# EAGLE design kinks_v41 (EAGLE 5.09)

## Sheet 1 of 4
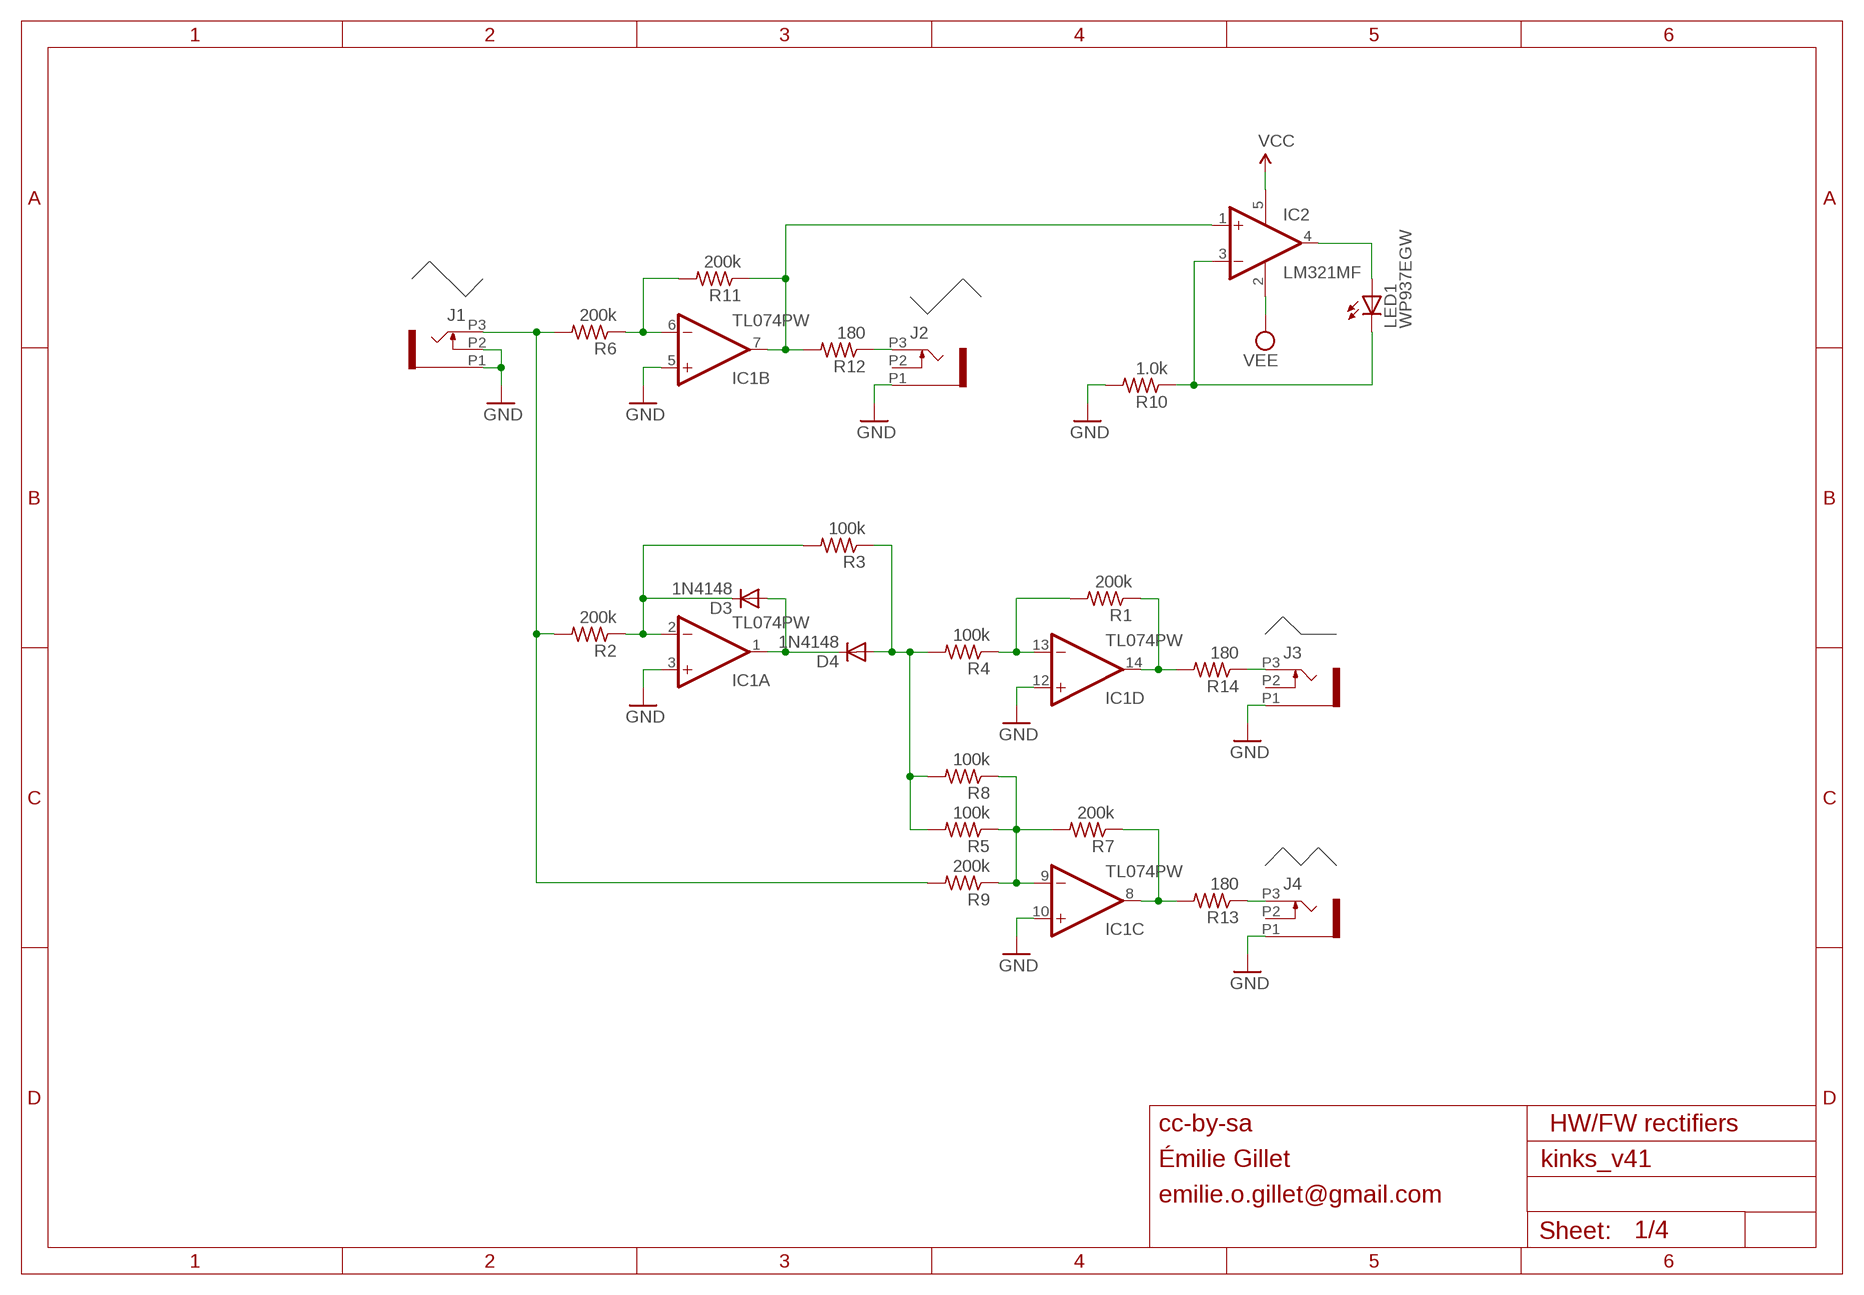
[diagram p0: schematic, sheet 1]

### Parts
D3  1N4148  DIODE-SOD523  [SOD523]
D4  1N4148  DIODE-SOD523  [SOD523]
IC1  TL074PW  [TSSOP14]
IC2  LM321MF  [SOT23-5]
J1  PJ301_THONKICONN6  [WQP_PJ_301M6]
J2  PJ301_THONKICONN6  [WQP_PJ_301M6]
J3  PJ301_THONKICONN6  [WQP_PJ_301M6]
J4  PJ301_THONKICONN6  [WQP_PJ_301M6]
LED1  WP937EGW  LED3MM  [LED3MM]
R1  200k  R-US_R0402  [R0402]
R2  200k  R-US_R0402  [R0402]
R3  100k  R-US_R0402  [R0402]
R4  100k  R-US_R0402  [R0402]
R5  100k  R-US_R0402  [R0402]
R6  200k  R-US_R0402  [R0402]
R7  200k  R-US_R0402  [R0402]
R8  100k  R-US_R0402  [R0402]
R9  200k  R-US_R0402  [R0402]
R10  1.0k  R-US_R0402  [R0402]
R11  200k  R-US_R0402  [R0402]
R12  180  R-US_R0402  [R0402]
R13  180  R-US_R0402  [R0402]
R14  180  R-US_R0402  [R0402]

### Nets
GND: IC1.3(A:+IN) IC1.5(B:+IN) IC1.10(C:+IN) IC1.12(D:+IN) J1.P1 J1.P2 J2.P1 J3.P1 J4.P1 R10.2 ; also sheet 2,3,4
N$9: IC2.3(-IN) LED1.K(C) R10.1
N$11: IC2.4(OUT) LED1.A
N$21: IC1.6(B:-IN) R6.1 R11.2
N$23: IC1.7(B:OUT) IC2.1(+IN) R11.1 R12.2
N$24: J2.P3 R12.1
N$25: D3.C IC1.2(A:-IN) R2.1 R3.2
N$26: D3.A D4.C IC1.1(A:OUT)
N$27: IC1.14(D:OUT) R1.1 R14.2
N$28: IC1.13(D:-IN) R1.2 R4.1
N$32: J3.P3 R14.1
N$33: IC1.9(C:-IN) R5.1 R7.2 R8.1 R9.1
N$34: J4.P3 R13.1
N$35: IC1.8(C:OUT) R7.1 R13.2
N$38: J1.P3 R2.2 R6.2 R9.2
N$39: D4.A R3.1 R4.2 R5.2 R8.2
VCC: IC2.5(V+) ; also sheet 2,3,4
VEE: IC2.2(V-) ; also sheet 2,3,4
Unconnected: J2.P2 J3.P2 J4.P2

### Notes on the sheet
- cc-by-sa | HW/FW rectifiers
- Émilie Gillet
- emilie.o.gillet@gmail.com

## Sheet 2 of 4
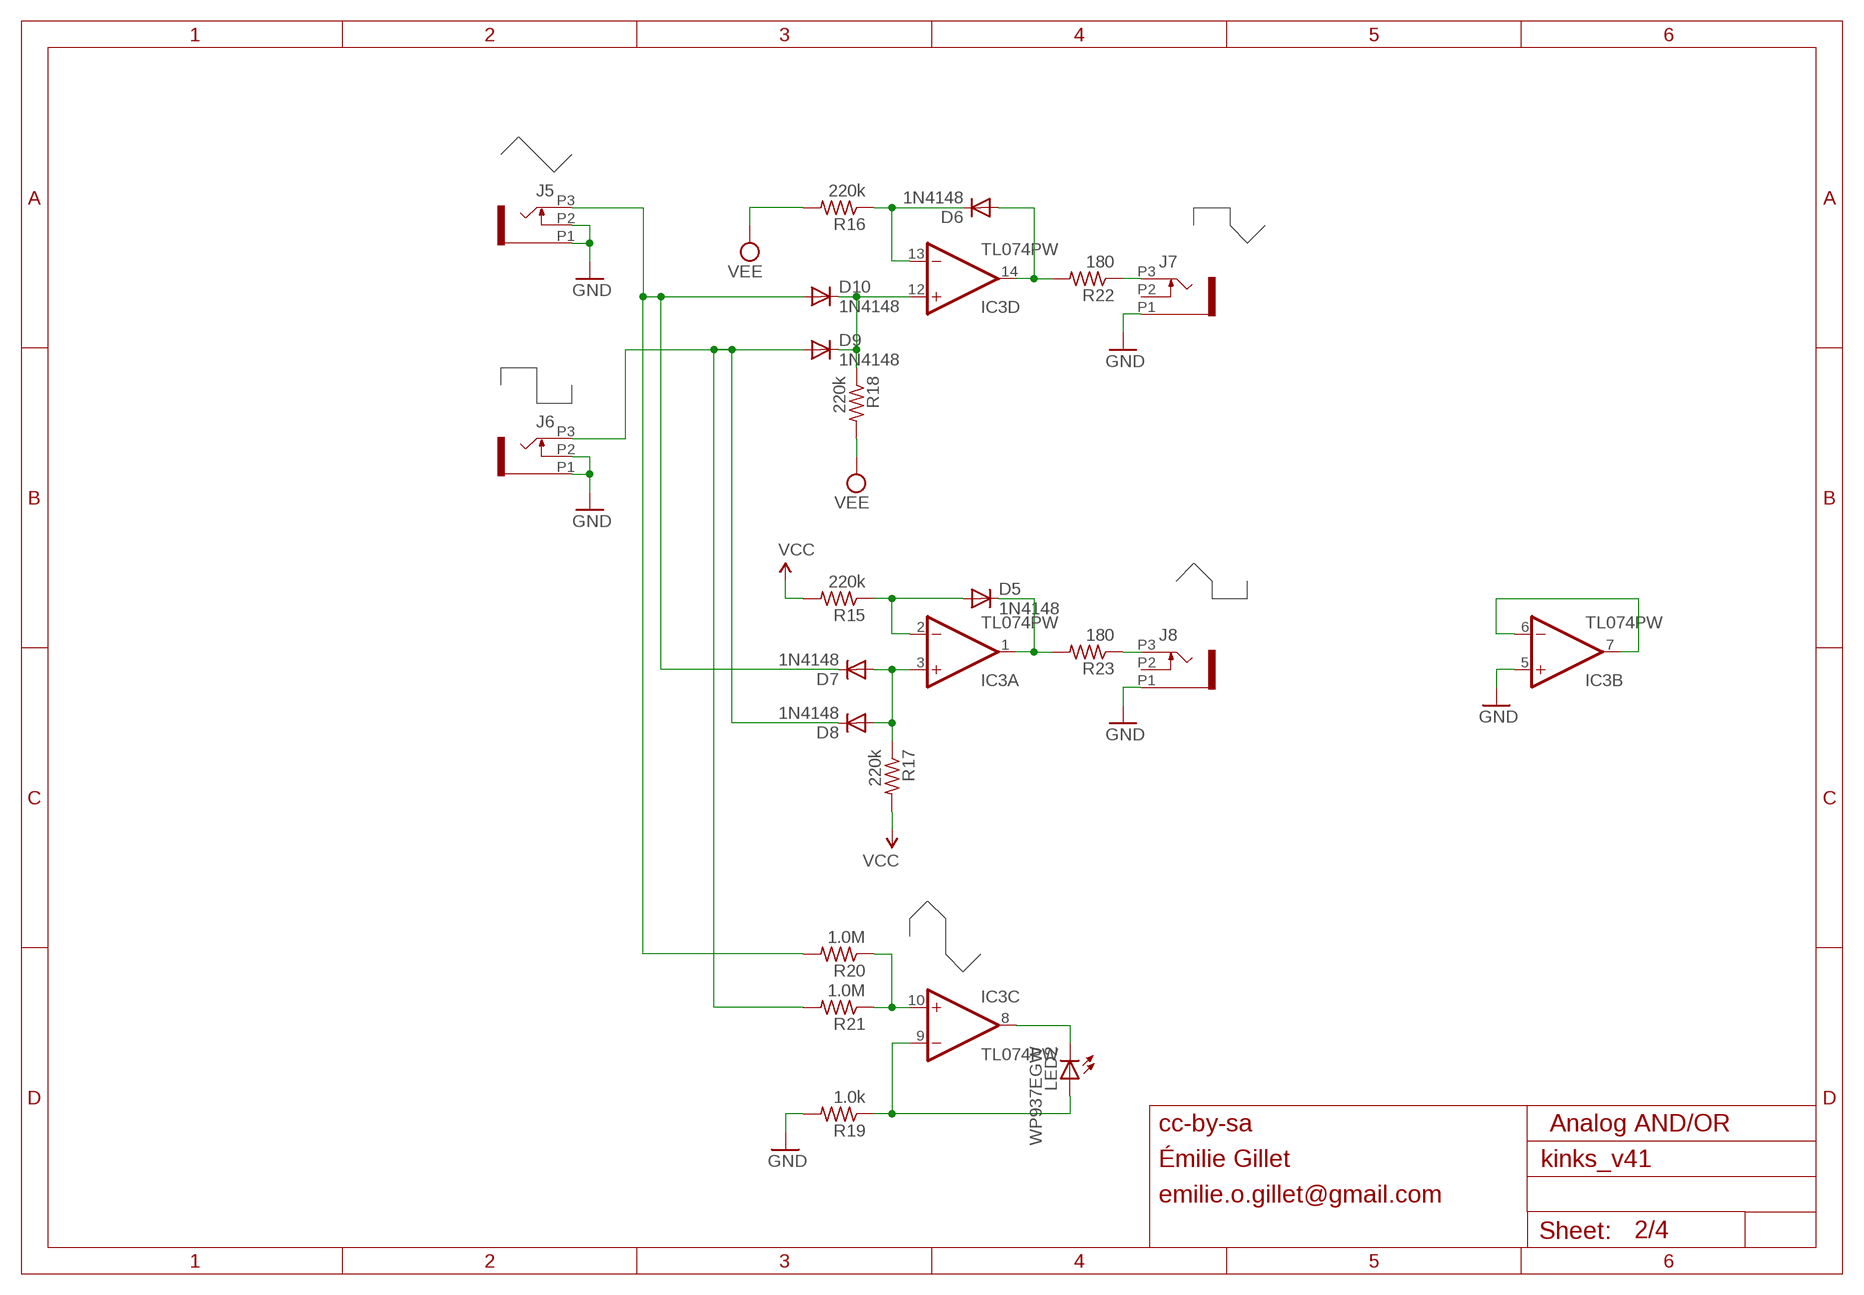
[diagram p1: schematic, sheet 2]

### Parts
D5  1N4148  DIODE-SOD523  [SOD523]
D6  1N4148  DIODE-SOD523  [SOD523]
D7  1N4148  DIODE-SOD523  [SOD523]
D8  1N4148  DIODE-SOD523  [SOD523]
D9  1N4148  DIODE-SOD523  [SOD523]
D10  1N4148  DIODE-SOD523  [SOD523]
IC3  TL074PW  [TSSOP14]
J5  PJ301_THONKICONN6  [WQP_PJ_301M6]
J6  PJ301_THONKICONN6  [WQP_PJ_301M6]
J7  PJ301_THONKICONN6  [WQP_PJ_301M6]
J8  PJ301_THONKICONN6  [WQP_PJ_301M6]
LED2  WP937EGW  LED3MM  [LED3MM]
R15  220k  R-US_R0402  [R0402]
R16  220k  R-US_R0402  [R0402]
R17  220k  R-US_R0402  [R0402]
R18  220k  R-US_R0402  [R0402]
R19  1.0k  R-US_R0402  [R0402]
R20  1.0M  R-US_R0402  [R0402]
R21  1.0M  R-US_R0402  [R0402]
R22  180  R-US_R0402  [R0402]
R23  180  R-US_R0402  [R0402]

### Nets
A: D7.C D10.A J5.P3 R20.2
B: D8.C D9.A J6.P3 R21.2
GND: IC3.5(B:+IN) J5.P1 J5.P2 J6.P1 J6.P2 J7.P1 J8.P1 R19.2 ; also sheet 1,3,4
N$1: D9.C D10.C IC3.12(D:+IN) R18.1
N$2: D6.A IC3.14(D:OUT) R22.2
N$4: D6.C IC3.13(D:-IN) R16.1
N$5: D7.A D8.A IC3.3(A:+IN) R17.1
N$7: IC3.6(B:-IN) IC3.7(B:OUT)
N$10: D5.C IC3.1(A:OUT) R23.2
N$14: IC3.8(C:OUT) LED2.K(C)
N$15: D5.A IC3.2(A:-IN) R15.1
N$17: J8.P3 R23.1
N$18: IC3.10(C:+IN) R20.1 R21.1
N$29: IC3.9(C:-IN) LED2.A R19.1
N$47: J7.P3 R22.1
VCC: R15.2 R17.2 ; also sheet 1,3,4
VEE: R16.2 R18.2 ; also sheet 1,3,4
Unconnected: J7.P2 J8.P2

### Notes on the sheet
- cc-by-sa | Analog AND/OR
- Émilie Gillet
- emilie.o.gillet@gmail.com

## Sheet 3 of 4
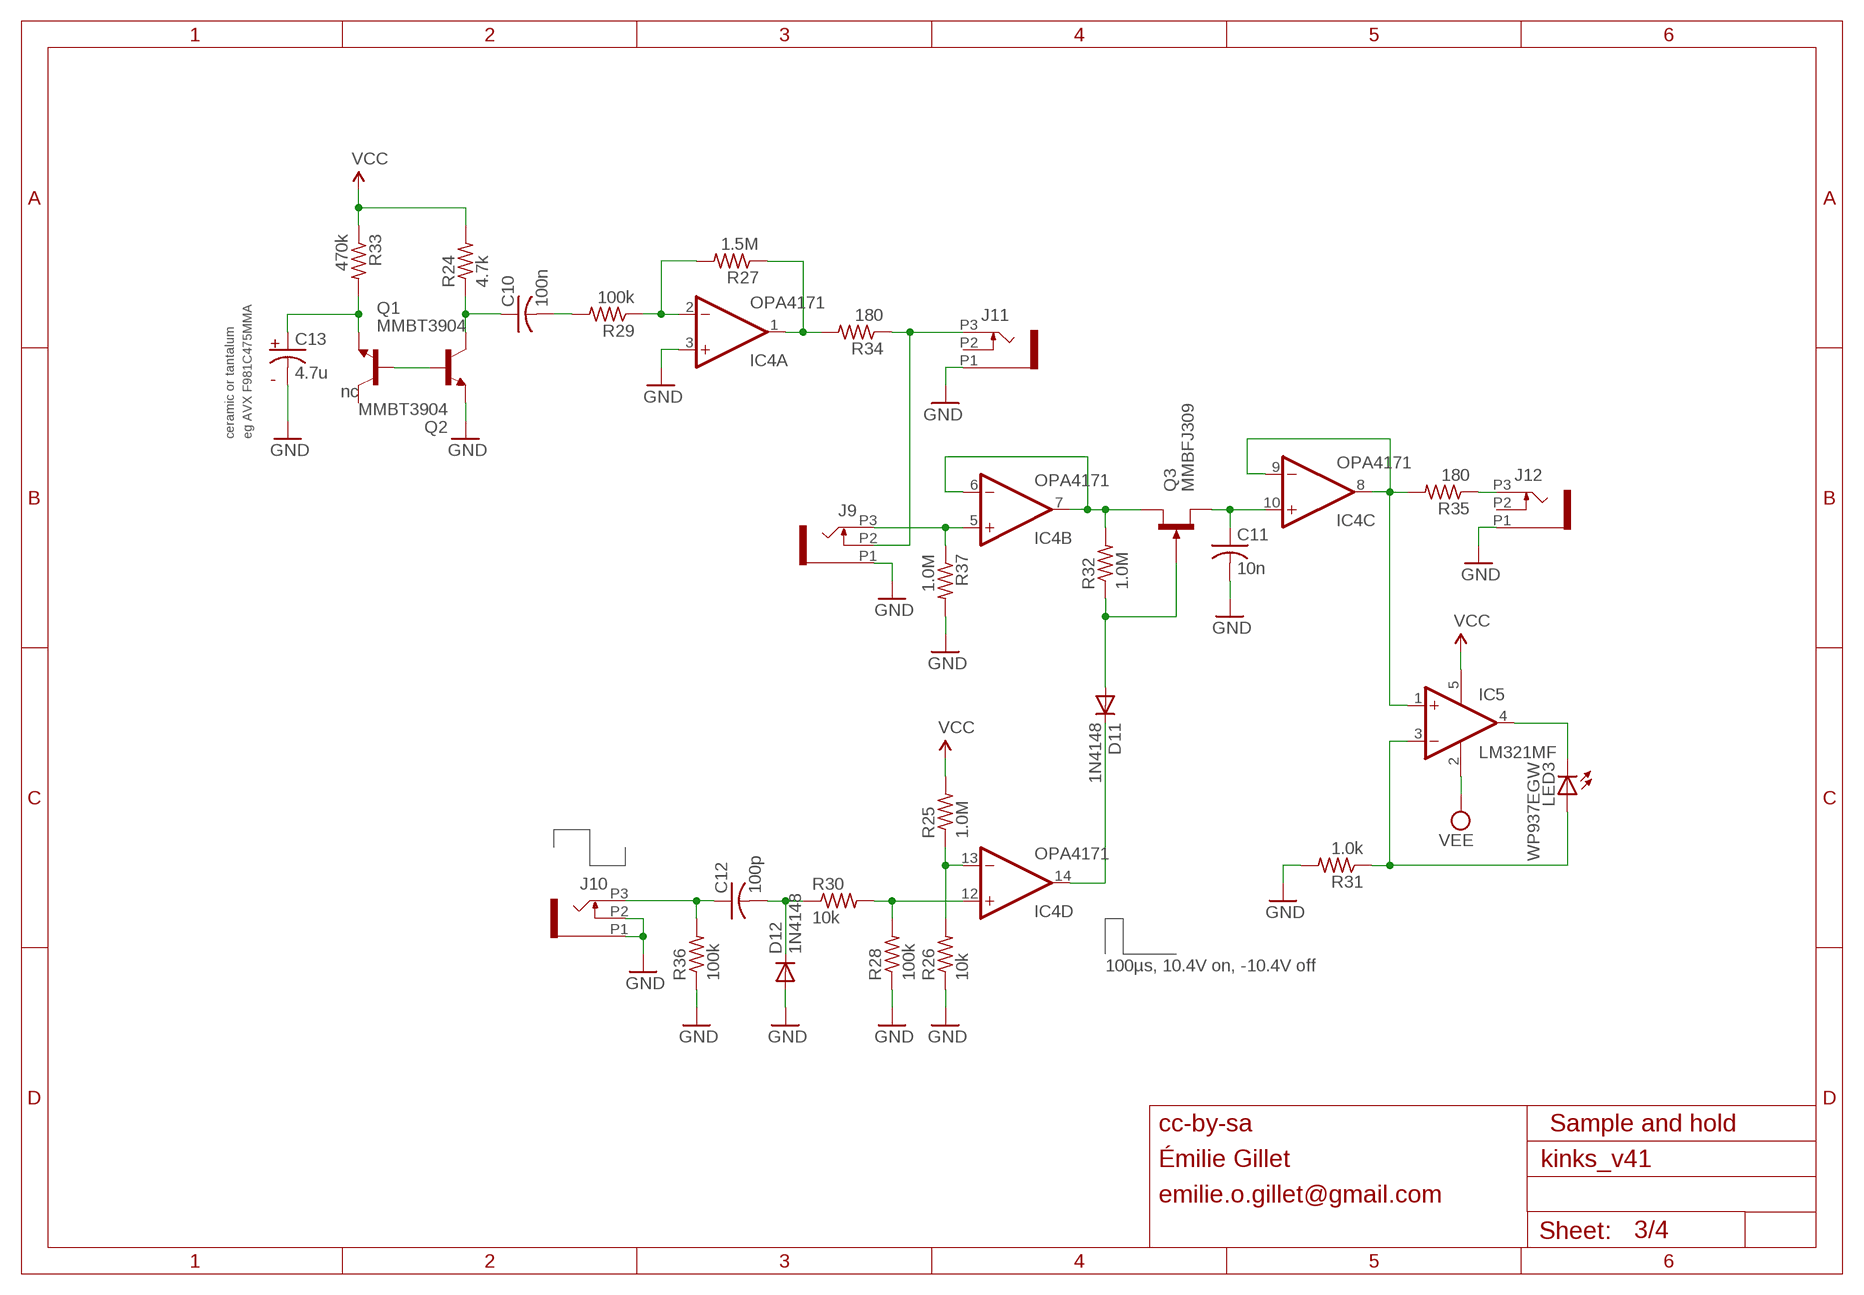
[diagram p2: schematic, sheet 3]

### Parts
C10  100n  C-USC0402  [C0402]
C11  10n  C-USC0603  [C0603]
C12  100p  C-USC0402  [C0402]
C13  4.7u  C-USC0603  [C0603]
D11  1N4148  DIODE-SOD523  [SOD523]
D12  1N4148  DIODE-SOD523  [SOD523]
IC4  OPA4171  TL074PW  [TSSOP14]
IC5  LM321MF  [SOT23-5]
J9  PJ301_THONKICONN6  [WQP_PJ_301M6]
J10  PJ301_THONKICONN6  [WQP_PJ_301M6]
J11  PJ301_THONKICONN6  [WQP_PJ_301M6]
J12  PJ301_THONKICONN6  [WQP_PJ_301M6]
LED3  WP937EGW  LED3MM  [LED3MM]
Q1  MMBT3904  MMBT3904LT1-NPN-SOT23-BEC  [SOT23-BEC]
Q2  MMBT3904  MMBT3904LT1-NPN-SOT23-BEC  [SOT23-BEC]
Q3  MMBFJ309  MMBFJ3  [SOT23]
R24  4.7k  R-US_R0402  [R0402]
R25  1.0M  R-US_R0402  [R0402]
R26  10k  R-US_R0402  [R0402]
R27  1.5M  R-US_R0402  [R0402]
R28  100k  R-US_R0402  [R0402]
R29  100k  R-US_R0402  [R0402]
R30  10k  R-US_R0402  [R0402]
R31  1.0k  R-US_R0402  [R0402]
R32  1.0M  R-US_R0402  [R0402]
R33  470k  R-US_R0402  [R0402]
R34  180  R-US_R0402  [R0402]
R35  180  R-US_R0402  [R0402]
R36  100k  R-US_R0402  [R0402]
R37  1.0M  R-US_R0402  [R0402]

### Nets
GND: C11.2 C13.2 D12.A IC4.3(A:+IN) J9.P1 J10.P1 J10.P2 J11.P1 J12.P1 Q1.E R26.1 R28.1 R31.2 R36.1 R37.2 ; also sheet 1,2,4
N$3: IC4.8(C:OUT) IC4.9(C:-IN) IC5.1(+IN) R35.2
N$8: Q1.B Q2.B
N$12: C13.1 Q2.E R33.2
N$13: C10.2 R29.2
N$16: IC4.2(A:-IN) R27.2 R29.1
N$19: IC5.3(-IN) LED3.A R31.1
N$30: IC5.4(OUT) LED3.K(C)
N$31: C10.1 Q1.C R24.1
N$36: IC4.1(A:OUT) R27.1 R34.2
N$37: J9.P2 J11.P3 R34.1
N$40: IC4.5(B:+IN) J9.P3 R37.1
N$41: IC4.6(B:-IN) IC4.7(B:OUT) Q3.1(D) R32.2
N$42: D11.A Q3.3(G) R32.1
N$43: D11.C IC4.14(D:OUT)
N$45: C11.1 IC4.10(C:+IN) Q3.2(S)
N$46: IC4.12(D:+IN) R28.2 R30.2
N$48: J12.P3 R35.1
N$49: C12.1 J10.P3 R36.2
N$50: IC4.13(D:-IN) R25.1 R26.2
N$51: C12.2 D12.C R30.1
VCC: IC5.5(V+) R24.2 R25.2 R33.1 ; also sheet 1,2,4
VEE: IC5.2(V-) ; also sheet 1,2,4
Unconnected: J11.P2 J12.P2 Q2.C

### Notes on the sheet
- +
- - | nc
- ceramic or tantalum | eg AVX F981C475MMA
- 100µs, 10.4V on, -10.4V off
- cc-by-sa | Sample and hold
- Émilie Gillet
- emilie.o.gillet@gmail.com

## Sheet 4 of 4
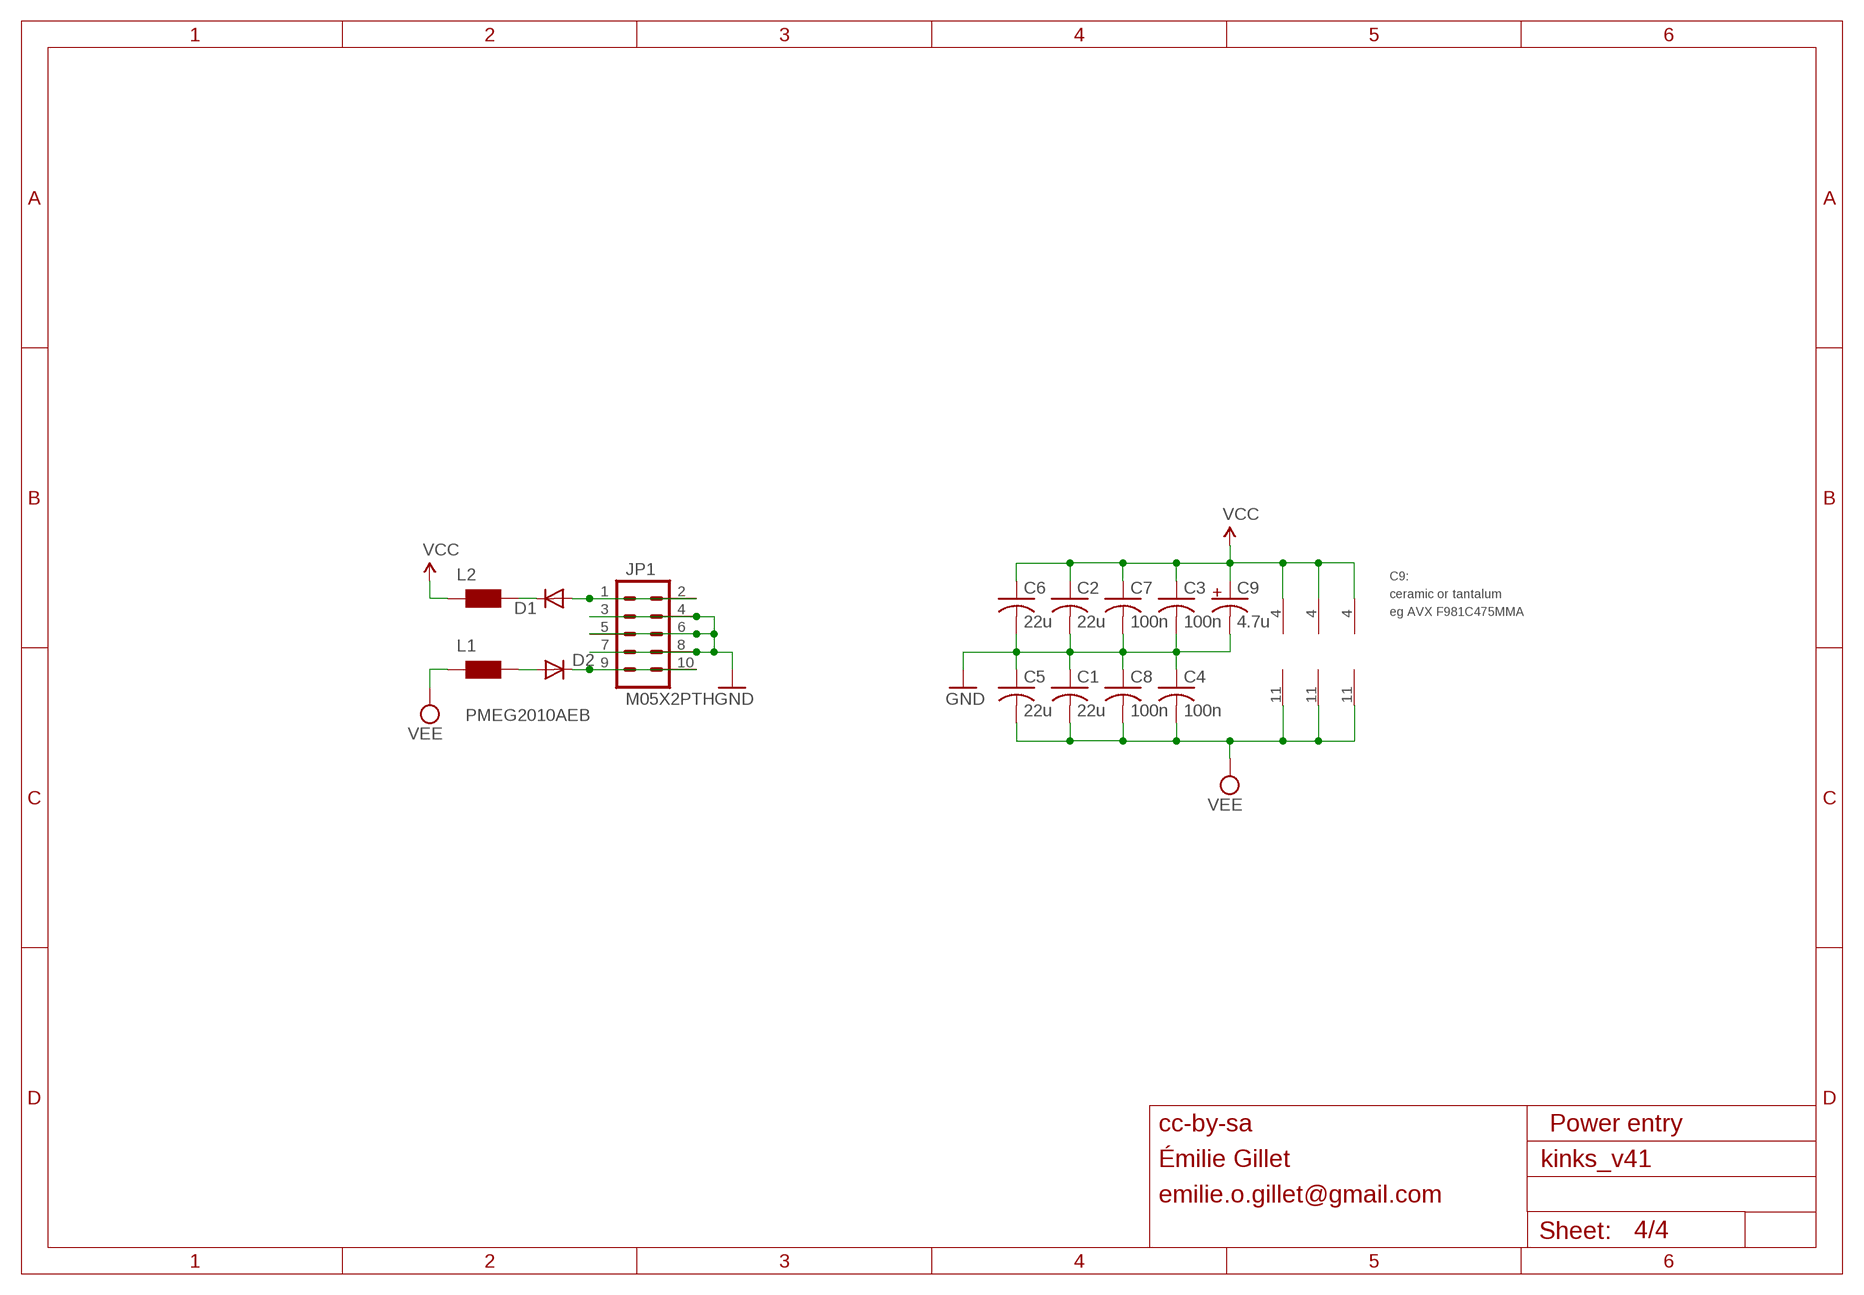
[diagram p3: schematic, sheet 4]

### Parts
C1  22u  C-USC0805  [C0805]
C2  22u  C-USC0805  [C0805]
C3  100n  C-USC0402  [C0402]
C4  100n  C-USC0402  [C0402]
C5  22u  C-USC0805  [C0805]
C6  22u  C-USC0805  [C0805]
C7  100n  C-USC0402  [C0402]
C8  100n  C-USC0402  [C0402]
C9  4.7u  C-USC0603  [C0603]
D1  PMEG2010AEB  DIODE-SOD523  [SOD523]
D2  PMEG2010AEB  DIODE-SOD523  [SOD523]
JP1  M05X2PTH  [AVR_ICSP]
L1  WE-CBF_0603  [0603]
L2  WE-CBF_0603  [0603]

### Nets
GND: C1.1 C2.2 C3.2 C4.1 C5.1 C6.2 C7.2 C8.1 C9.2 JP1.3 JP1.4 JP1.5 JP1.6 JP1.7 JP1.8 ; also sheet 1,2,3
N$6: D1.A JP1.1 JP1.2
N$20: D2.C JP1.9 JP1.10
N$22: D1.C L2.2
N$44: D2.A L1.2
VCC: C2.1 C3.1 C6.1 C7.1 C9.1 IC1.4(P:V+) IC3.4(P:V+) IC4.4(P:V+) L2.1 ; also sheet 1,2,3
VEE: C1.2 C4.2 C5.2 C8.2 IC1.11(P:V-) IC3.11(P:V-) IC4.11(P:V-) L1.1 ; also sheet 1,2,3

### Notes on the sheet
- C9:
- + | ceramic or tantalum
- eg AVX F981C475MMA
- cc-by-sa | Power entry
- Émilie Gillet
- emilie.o.gillet@gmail.com

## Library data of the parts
C1-C13 = rcl:C-US: CAPACITOR, American symbol
D1-D12 = diode:DIODE-: DIODE
IC1 IC3 IC4 = linear:TL074: OP AMP
IC2 IC5 = linear:LM321?*: Low Power Single Op Amp Source: http://cache.national.com/ds/LM/LM321.pdf
J1-J12 = og-pj301:PJ301_THONKICONN
JP1 = og-header:M05X2: Header 5x2 Standard 10-pin dual row 0.1" header. Commonly used with AVR-ISP. Use with Spark Fun Electronics SKU: PRT-00778
L1 L2 = wuerth-elektronik:WE-CBF: SMD EMI Suppression Ferrite Beads
LED1-LED3 = led:LED: LED
Q1 Q2 = transistor:*-NPN-: NPN Transistror BF959 corrected 2008.03.06
Q3 = transistor-small-signal:MMBFJ3*: N-Channel RF Amplifier Source: http://www.fairchildsemi.com/pf/J3/J310.html
R1-R37 = rcl:R-US_: RESISTOR, American symbol

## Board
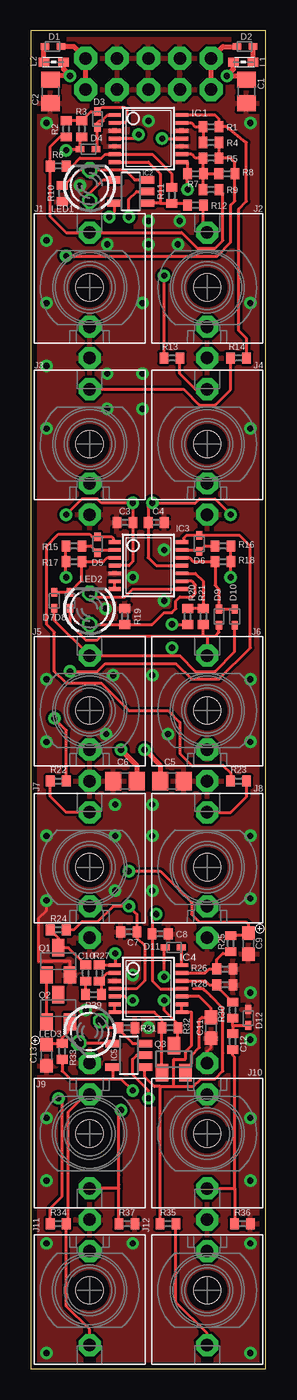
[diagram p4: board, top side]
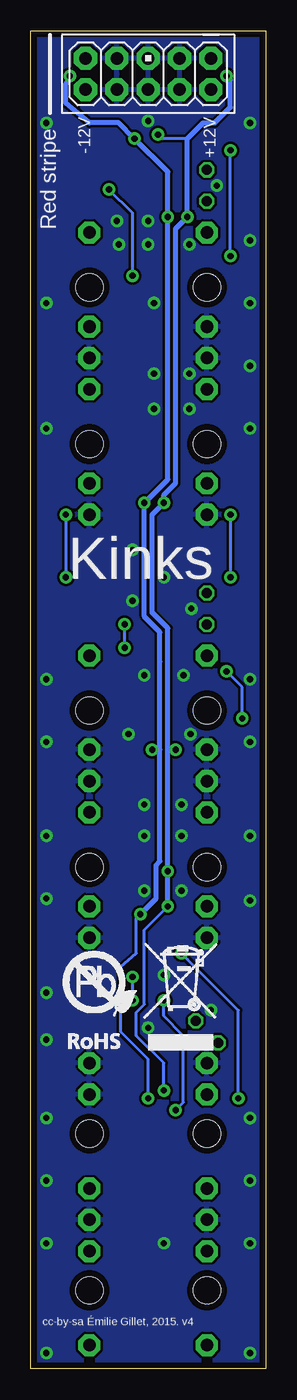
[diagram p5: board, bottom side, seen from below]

Size 19.03 x 108.43 mm. Coordinates in mm from the lower left corner, seen from the top.
Outline: 0,0 19.03,0 19.03,108.43 0,108.43 0,0
Copper layers (1*16): Top 0.035mm / dielectric 1.5mm / Bottom 0.035mm
Design rules "PCBCart-Standard *": minimum track width 8mil, minimum drill 0.4mm, track to track 8mil, track to pad 8mil, pad to pad 8mil, via to via 8mil, smd to smd 8mil, copper to edge 20mil, drill to drill 8mil, minimum pad ring 8mil, minimum via ring 10mil, stop-mask expansion 3mil, vias tented up to drill 25mil, thermal gap 8mil

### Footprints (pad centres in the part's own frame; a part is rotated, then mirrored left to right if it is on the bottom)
C0805 = smd 1.3 x 1.5: 1 -0.95,0; 2 0.95,0
C0402 = smd 0.7 x 0.9: 1 -0.65,0; 2 0.65,0
C0603 = smd 1.1 x 1: 1 -0.85,0; 2 0.85,0
SOD523 = smd 0.7 x 0.5: A 0.7,0; C -0.6,0
TSSOP14 = smd 0.305 x 0.991: 1 -1.905,-2.718; 2 -1.27,-2.718; 3 -0.635,-2.718; 4 0,-2.718; 5 0.635,-2.718; 6 1.27,-2.718; 7 1.905,-2.718; 8 1.905,2.718; 9 1.27,2.718; 10 0.635,2.718; 11 0,2.718; 12 -0.635,2.718; 13 -1.27,2.718; 14 -1.905,2.718
SOT23-5 = smd 0.6 x 1.2: 1 -0.95,-1.306; 2 0,-1.306; 3 0.95,-1.306; 4 0.95,1.306; 5 -0.95,1.306
WQP_PJ_301M6 = drill 1.016 pad 1.778 octagon: P1 0,-5.715; P2 0,-3.175; P3 0,4.445 | hole 2.2: 0,0
AVR_ICSP = drill 1.016 pad 1.88 octagon: 1 -1.27,5.08; 2 1.27,5.08; 3 -1.27,2.54; 4 1.27,2.54; 5 -1.27,0; 6 1.27,0; 7 -1.27,-2.54; 8 1.27,-2.54; 9 -1.27,-5.08; 10 1.27,-5.08
0603 = smd 0.85 x 0.7: 1 -0.9,0; 2 0.7,0
LED3MM = drill 0.813 octagon: A -1.27,0; K 1.27,0
SOT23-BEC = smd 1 x 1.4: B -0.95,-1.1; C 0,1.1; E 0.95,-1.1
SOT23 = smd 1 x 1.4: 1 -0.95,-1.1; 2 0.95,-1.1; 3 0,1.1
R0402 = smd 0.7 x 0.9: 1 -0.65,0; 2 0.65,0

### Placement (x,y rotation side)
C1  17.46,103.51 90 top
C2  1.59,103.5 270 top
C3  7.62,68.58 180 top
C4  10.16,68.58 180 top
C5  11.43,47.63 180 top
C6  7.62,47.63 180 top
C7  7.94,35.4 180 top
C8  10.48,35.24 180 top
C9  17.62,34.45 270 top
C10  4.45,32.07 270 top
C11  14.61,27.62 270 top
C12  16.35,26.51 90 top
C13  1.27,25.4 270 top
D1  1.75,107.16 0 top
D2  17.3,107.16 0 top
D3  5.4,101.28 270 top
D4  4.68,98.82 180 top
D5  5.4,66.83 270 top
D6  13.65,66.83 90 top
D7  1.91,62.23 90 top
D8  3.17,62.23 90 top
D9  15.24,60.96 270 top
D10  16.51,60.96 270 top
D11  11.59,34.13 180 top
D12  17.62,28.42 90 top
IC1  9.53,99.69 270 top
IC2  8.1,95.41 90 top
IC3  9.53,65.09 270 top
IC4  9.53,30.8 270 top
IC5  7.94,25.4 90 top
J1  4.76,87.63 0 top
J2  14.29,87.63 0 top
J3  4.76,74.93 0 top
J4  14.29,74.93 0 top
J5  4.76,53.34 0 top
J6  14.29,53.34 0 top
J7  4.76,40.64 0 top
J8  14.29,40.64 0 top
J9  4.76,19.05 180 top
J10  14.29,19.05 180 top
J11  4.76,6.35 180 top
J12  14.29,6.35 180 top
JP1  9.53,104.93 270 bottom
L1  17.3,105.89 0 top
L2  1.75,105.89 180 top
LED1  4.76,95.89 90 top
LED2  4.76,61.59 90 top
LED3  4.76,27.3 225 top
Q1  2.22,33.02 0 top
Q2  2.22,29.21 0 top
Q3  11.59,25.08 0 top
R1  14.61,100.65 180 top
R2  2.86,100.49 270 top
R3  4.13,100.49 90 top
R4  14.61,99.38 0 top
R5  14.61,98.11 0 top
R6  2.22,97.47 180 top
R7  13.34,96.84 0 top
R8  15.88,96.84 0 top
R9  14.61,95.57 0 top
R10  2.54,95.25 270 top
R11  11.43,95.09 90 top
R12  13.34,94.3 180 top
R13  11.43,81.92 180 top
R14  16.83,81.92 0 top
R15  3.49,66.67 180 top
R16  15.56,66.67 0 top
R17  3.49,65.41 180 top
R18  15.56,65.41 0 top
R19  7.62,60.96 90 top
R20  12.7,60.96 270 top
R21  13.97,60.96 270 top
R22  2.22,47.62 0 top
R23  16.83,47.62 180 top
R24  2.22,35.56 0 top
R25  16.19,34.45 90 top
R26  15.72,32.38 180 top
R27  5.56,32.07 270 top
R28  15.72,31.11 180 top
R29  5.08,30.32 180 top
R30  16.35,29.05 90 top
R31  7.78,27.62 0 top
R32  11.27,27.62 180 top
R33  2.54,25.72 90 top
R34  2.22,11.75 180 top
R35  11.11,11.75 180 top
R36  17.14,11.75 180 top
R37  7.78,11.75 0 top
U$2  [ROHS]  17.3,25.24 0 bottom

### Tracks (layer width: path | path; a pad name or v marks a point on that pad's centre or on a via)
A  (via drill 0.5)
  Top 0.254: 11.43,57.78 J5.P3 1.91,60.64 D7.C | 11.43,57.78 12.06,57.78 13.34,56.52 14.92,56.52 16.51,58.1 D10.A | R20.2 12.69,60.33 v11.43,60.33 | 11.43,57.78 v11.43,58.42
  Bottom 0.254: v11.43,58.42 v11.43,60.33
B
  Top 0.254: 13.97,59.37 5.71,59.37 5.4,59.05 4.45,59.05 3.17,60.33 D8.C | 13.97,59.37 14.29,59.37 | 14.29,59.37 14.92,59.37 15.24,59.69 D9.A | 13.97,59.37 R21.2 | 14.29,59.37 J6.P3
GND  (via drill 0.5)
  Top 0.254: J10.P1 14.29,25.72 14.61,26.04 C11.2 | Q1.E 3.17,33.02 0.64,33.02 0.64,36.51 1.27,37.15 v1.27,37.94
  other vias: 8.26,64.14 10.79,66.36 3.97,95.89 9.53,101.12 9.05,77.79 6.19,80.64 1.27,55.88 9.53,91.12 17.78,30.48 8.26,10.16 6.83,43.18 9.84,45.72 1.27,1.27 17.78,1.27 17.78,10.16 1.27,10.16 17.78,15.24 1.27,15.24 1.27,20.32 17.78,20.32 17.78,26.67 17.78,38.1 17.78,43.18 1.27,43.18 1.27,76.2 1.27,100.97 17.78,100.97 9.84,43.18 8.25,31.91 6.19,91.12 9.05,80.64 11.91,91.12 17.78,55.88 6.19,77.79 1.27,50.8 17.78,50.8 6.1,51.43 11.11,51.43 17.78,76.2 1.27,81.28 1.27,86.36 1.27,91.44 17.78,86.36 9.05,86.36 9.52,27.62 6.83,38.73 9.84,38.73 4.44,29.05 9.84,56.2 6.83,45.72 9.53,93.03 12.06,93.03 6.03,61.59 10.79,62.23 6.67,56.2
  pour Bottom: 0,108.43 0,0 19.05,0 19.05,108.43
  pour Top: 0,108.43 0,0 19.05,0 19.05,108.43
N$1
  Top 0.254: IC3.12 12.86,65.72 13.18,65.41 R18.1 14.92,65.39 14.92,63.5 15.24,63.18 D9.C D10.C
N$2  (via drill 0.5)
  Top 0.254: D6.A 13.72,67.63 | v3.17,56.52 5.4,56.52 6.03,57.15 11.75,57.15 13.02,55.88 15.24,55.88 17.78,58.42 17.78,66.67 16.92,67.53 D6.A | v1.91,52.7 2.87,51.74 R22.2 | IC3.14 12.38,67.13 12.38,67.31 12.61,67.53 D6.A
  Bottom 0.254: v3.17,56.52 1.91,55.24 v1.91,52.7
N$3
  Top 0.254: IC4.9 | IC4.8 | IC4.8 12.22,28.87 | IC4.8 | 10.48,22.86 11.59,22.86 | 11.59,22.86 13.18,22.86 13.81,23.5 14.92,23.5 15.56,24.13 15.56,25.56 15.56,29.21 14.61,30.16 14.29,30.48 13.97,30.8 13.34,30.8 13.18,30.8 | R35.2 10.48,11.76 10.48,22.86 | 11.59,22.86 11.59,25.08 12.54,25.08 12.54,25.72 13.02,26.19 13.02,28.89 IC4.8 | IC4.8 IC4.9 | IC5.1 9.21,24.25 9.21,23.65 10,22.86 10.48,22.86
N$4
  Top 0.254: R16.1 14.09,66.67 D6.C 13.53,66.36 IC3.13
N$5
  Top 0.254: IC3.3 6.19,65.72 5.87,65.41 R17.1 4.14,63.9 D8.A D7.A
N$6
  Top 0.406: JP1.2 JP1.1 3.49,107.16 D1.A
N$7
  Top 0.254: IC3.7 IC3.6
N$8
  Top 0.254: Q2.B Q1.B
N$9
  Top 0.254: IC2.3 8.42,96.36 7.62,97.16 LED1.K 3.97,97.16 2.71,95.9 R10.1
N$10
  Top 0.254: R23.2 16.18,48.27 15.56,48.9 13.02,48.9 12.06,49.85 12.06,52.39 11.11,53.34 7.94,53.34 5.71,55.56 2.86,55.56 1.91,56.52 1.91,59.69 1.27,60.33 1.27,66.67 2.22,67.63 4.76,67.63 4.96,67.43 D5.C | D5.C 5.43,67.59 | IC3.1 6.67,67.13 6.67,67.31 6.54,67.43 D5.C
N$11
  Top 0.254: LED1.A 4.76,95.25 5.87,96.36 IC2.4
N$12
  Top 0.254: C13.1 1.39,26.37 R33.2 2.54,26.83 3.02,27.3 3.02,27.95 Q2.E
N$13
  Top 0.254: R29.2 4.45,30.34 C10.2
N$14
  Top 0.254: LED2.K 5.08,62.55 7.62,62.55 8.26,63.18 IC3.8
N$15
  Top 0.254: R15.1 4.86,66.67 D5.A 5.62,66.36 IC3.2
N$16
  Top 0.254: IC4.2 6.19,32.07 5.56,31.43 R27.2 5.73,31.24 R29.1
N$17
  Top 0.254: J8.P3 16.19,45.09 17.48,46.37 R23.1
N$18
  Top 0.254: IC3.10 13.34,64.45 13.97,63.82 R21.1 R20.1
N$19
  Top 0.254: LED3.A 6.24,27.62 R31.1 7.13,27.48 8.26,26.35 IC5.3
N$20
  Top 0.406: JP1.10 JP1.9 15.56,107.16 D2.C
N$21
  Top 0.254: 2.86,97.47 R6.1 3.33,97.47 3.97,98.11 5.71,98.11 6.03,98.42 IC1.6 9.84,98.42 11.43,96.84 R11.2
N$22
  Top 0.406: D1.C 1.05,106.9 L2.2
N$23
  Top 0.254: IC1.7 9.53,97.79 10.48,96.84 10.48,94.46 | IC2.1 10.48,94.46 | 10.48,94.46 11.41,94.46 R11.1 12.54,94.44 R12.2
N$24
  Top 0.254: J2.P3 13.98,92.38 R12.1
N$25
  Top 0.254: IC1.2 7.62,100.97 7.78,101.12 7.78,102.08 7.62,102.23 5.75,102.23 D3.C 4.87,101.88 R3.2 R2.1
N$26
  Top 0.254: D4.C 5.24,98.87 5.4,99.03 D3.A 5.4,100.97 5.56,101.12 5.87,101.12 5.87,101.28 6.19,101.6 IC1.1
N$27
  Top 0.254: IC1.14 14.92,101.6 15.26,101.27 R1.1 15.88,100.65 17.46,99.38 17.46,94.61 16.83,93.98 16.83,84.14 17.48,83.49 R14.2
N$28
  Top 0.254: IC1.13 13.02,100.97 13.34,100.65 R1.2 R4.1
N$29
  Top 0.254: IC3.9 13.02,63.82 13.34,63.5 13.34,62.87 13.02,62.55 12.06,62.55 11.75,62.23 11.75,61.59 11.43,61.28 10.79,61.28 9.83,60.31 R19.1 7.61,60.33 LED2.A
N$30
  Top 0.254: IC5.4 6.57,26.41 LED3.K
N$31
  Top 0.254: R24.1 2.22,34.91 Q1.C | Q1.C 2.55,34.12 | C10.1 3.04,34.12 Q1.C
N$32
  Top 0.254: R14.1 16.18,79.36 14.92,78.11 13.65,78.11 12.38,79.38 J3.P3
N$33
  Top 0.254: IC1.9 13.02,98.42 13.34,98.11 R5.1 | R5.1 | R9.1 13.98,95.6 R7.2 | R7.2 13.96,96.87 R5.1 | R7.2 R8.1
N$34
  Top 0.254: J4.P3 13.34,79.38 12.08,80.63 R13.1
N$35  (via drill 0.5)
  Top 0.254: v12.7,95.57 12.69,95.87 R7.1 12.7,96.85 12.7,97.79 IC1.8 | R13.2 10.79,81.93 v10.79,88.58
  Bottom 0.254: v12.7,95.57 10.79,93.66 v10.79,88.58
N$36  (via drill 0.5)
  Top 0.254: R34.2 1.57,13 2.54,13.97 2.54,21.59 v2.22,21.91 | IC4.1 6.83,32.72 v6.83,33.66 | IC4.1 | R27.1 5.57,32.7 IC4.1
  Bottom 0.254: v6.83,33.66 6.35,33.18 2.22,29.05 v2.22,21.91
N$37
  Top 0.254: J11.P3 4.76,3.17 2.87,5.07 R34.1 3.02,11.8 3.02,20.8 4.45,22.23 J9.P2
N$38
  Top 0.254: R2.2 2.37,99.84 1.57,99.05 R6.2 1.57,93.36 2.86,92.08 J1.P3 12.22,92.08 13.49,90.81 14.92,90.81 15.56,91.44 15.56,95.23 15.24,95.55 R9.2
N$39  (via drill 0.5)
  Top 0.254: v2.86,98.74 2.94,98.82 D4.A 3.98,99.69 R3.1 | R4.2 R5.2 16.19,98.11 16.52,97.78 R8.2 16.52,94.63 16.19,94.3 16.19,91.28 15.08,90.17 v2.86,90.17
  Bottom 0.254: v2.86,90.17 v2.86,98.74
N$40  (via drill 0.5)
  Top 0.254: IC4.5 7.62,30.16 7.94,29.84 v8.26,29.84 | R37.1 7.13,14.61 | 7.13,14.61 7.13,14.92 7.13,15.7 7.13,20.78 v7.3,20.95 | 7.13,14.61 J9.P3
  Bottom 0.254: v8.26,29.84 8.26,28.57 6.67,26.99 6.67,21.59 v7.3,20.95
N$41
  Top 0.254: IC4.7 IC4.6 | IC4.7 | Q3.1 10.62,24 R32.2 10.64,27.64 10.64,28.26 10,28.89 7.94,28.89 | 7.94,28.89 | 7.94,28.89 IC4.7
N$42  (via drill 0.5)
  Top 0.254: v10.79,29.84 10.79,29.05 11.92,27.93 R32.1 11.92,26.52 Q3.3 11.6,26.2 | D11.A 10.79,34.04 v10.79,31.75
  Bottom 0.254: v10.79,29.84 v10.79,31.75
N$43
  Top 0.254: IC4.14 12.24,34.08 D11.C
N$44
  Top 0.406: L1.2 D2.A
N$45
  Top 0.254: IC4.10 13.65,30.16 14.61,29.21 C11.1 13.87,28.47 13.65,28.26 13.65,26.04 13.02,25.4 13.02,24.77 12.7,24.45 12.7,24.14 Q3.2
N$46
  Top 0.254: IC4.12 14.13,31.43 14.45,31.11 R28.2 | R28.2 | R30.2 15.07,30.99 R28.2
N$47
  Top 0.254: J7.P3 2.86,45.09 1.57,46.37 R22.1
N$48
  Top 0.254: J12.P3 14.29,2.86 11.75,5.4 11.75,11.73 R35.1
N$49
  Top 0.254: J10.P3 16.51,14.61 | R36.2 16.51,11.76 16.51,14.61 | 16.51,14.61 16.51,25.24 16.35,25.4 C12.1
N$50
  Top 0.254: R25.1 16.19,33.6 16.14,33.66 15.56,33.66 15.07,33.16 R26.2 14.45,32.38 14.13,32.07 IC4.13
N$51
  Top 0.254: 16.35,27.78 R30.1 | D12.C 17.59,27.78 16.35,27.78 | 16.35,27.78 | 16.35,27.78 C12.2
VCC  (via drill 0.5)
  Top 0.254: IC3.4 7.94,65.09 8.27,65.42 C3.1 8.26,68.59 v8.26,70.17 5.71,70.17 5.4,70.48 4.13,70.48 v2.86,69.22 | v8.73,100.01 8.41,99.69 IC1.4 | 16.19,35.3 R25.2 17.42,35.1 C9.1 17.62,36.04 17.46,36.2 13.65,36.2 13.02,36.83 13.02,37.78 10.48,40.32 v7.94,40.32 | v6.35,93.34 6.79,93.78 IC2.5 | IC4.4 | IC4.4 8.57,30.8 9.21,31.43 9.21,34.29 8.57,34.92 8.57,35.23 C7.1 8.59,36.81 v7.94,37.47 | IC5.5 6.67,24.41 6.67,23.5 | 6.67,23.5 3.17,23.5 2.54,24.13 R33.1 | 6.67,23.5 7.3,23.5 v8.26,22.54 | v7.94,37.47 | R24.2 | R24.2 3.49,35.56 4.13,36.2 5.4,36.2 6.67,37.47 v7.94,37.47 | C6.1 | R15.2 R17.2 2.84,64.15 v2.86,64.14
  Top 0.406: C2.1 1.91,104.78 v3.17,104.78 2.65,105.3 L2.1 | C6.1 8.57,48.9 v7.3,50.16
  Bottom 0.254: 6.35,99.69 8.41,99.69 v8.73,100.01 | v7.94,37.47 9.84,35.56 9.84,29.53 10.48,28.89 10.48,26.99 8.26,24.77 v8.26,22.54 | v2.86,69.22 v2.86,64.14
  Bottom 0.406: v7.94,40.32 7.94,50.16 | 7.94,50.16 7.94,60.01 9.21,61.28 9.21,69.22 v8.26,70.17 8.26,70.8 7.3,71.75 7.3,92.39 v6.35,93.34 6.35,99.69 5.08,100.97 4.13,100.97 2.86,102.23 2.86,104.46 v3.17,104.78 | v7.94,37.47 | v7.94,40.32 | v7.94,37.47 v7.94,40.32 | 7.94,50.16 v7.3,50.16
VEE  (via drill 0.5)
  Top 0.254: IC4.11 | IC4.11 10.48,30.8 9.84,31.43 9.84,35.23 C8.2 9.83,36.5 v10.16,36.83 | v10.64,99.69 IC1.11 | v7.94,93.34 7.94,94.77 8.57,95.41 IC2.2 | IC3.11 10.16,65.09 9.51,65.74 C4.2 9.51,69.83 v9.84,70.17 13.34,70.17 13.65,70.48 14.92,70.48 v16.19,69.22 | IC5.2 8.57,25.4 8.26,25.08 8.26,23.81 9.53,22.54 v9.53,21.91 | C5.2 | R16.2 R18.2 16.19,65.39 v16.19,64.14
  Top 0.406: C1.2 17.14,104.78 v15.88,104.78 16.4,105.3 L1.1 | C5.2 10.48,48.9 v9.21,50.16
  Bottom 0.254: v10.16,36.83 10.48,36.51 10.48,33.66 11.75,32.54 11.75,27.3 9.53,25.08 v9.53,21.91 | v16.19,69.22 v16.19,64.14
  Bottom 0.406: 8.57,50.16 8.57,41.12 8.89,40.8 8.89,38.1 v10.16,36.83 | 8.57,50.16 8.57,57.31 8.57,59.69 9.53,60.64 9.84,60.96 v9.84,70.17 7.94,72.07 v7.94,93.34 7.94,97 v10.64,99.69 11.91,100.97 14.29,100.97 16.19,102.55 16.19,104.14 15.88,104.46 v15.88,104.78 | 8.57,50.16 v9.21,50.16

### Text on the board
bPlace: Red stripe
bNames: +12V | -12V | Kinks | cc-by-sa Émilie Gillet, 2015. v4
